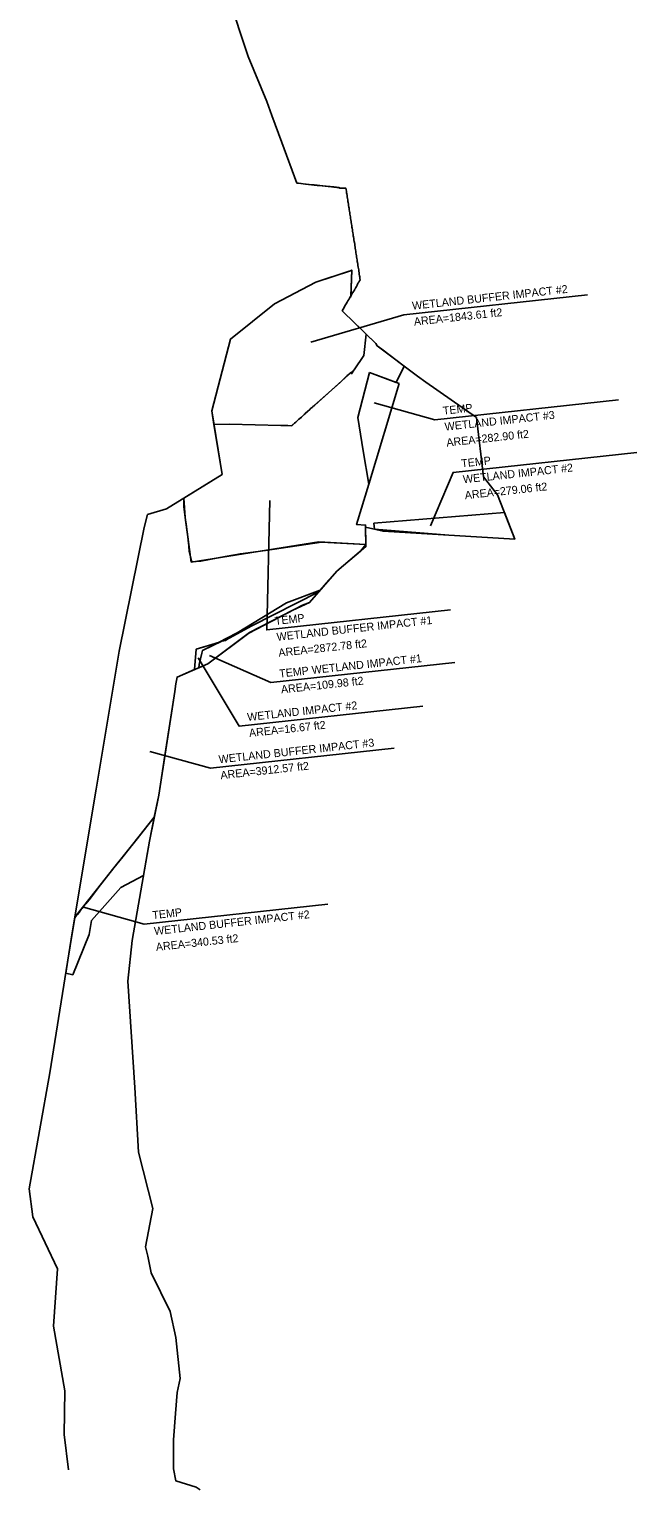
# Model space of a CAD drawing. Extents: x 1509173 to 1510536, y 401169 to 402191.
# Drawn here: x 1509752 to 1509965, y 401169 to 401680 of the extents above; entities that cross this region are included whole.
import ezdxf

# ---------------------------------------------------------------- set-up
doc = ezdxf.new("R2010")
doc.units = 0
for name, color, linetype in [('Default', 7, 'Continuous'), ('EWB_P', 7, 'Continuous'), ('LAWE', 7, 'Continuous'), ('LAWE_P_T', 7, 'Continuous'), ('Level 11', 7, 'Continuous'), ('Level 12', 7, 'Continuous')]:
    doc.layers.add(name, color=color, linetype=linetype)

msp = doc.modelspace()

# ---------------------------------------------------------------- linework, layer by layer
at = {"layer": 'Default'}
for p, q in [((1509864.2, 401595.49), (1509852.48, 401591.74)), ((1509864.65, 401595.7), (1509864.2, 401595.49)), ((1509865.1, 401595.9), (1509864.65, 401595.7)), ((1509864.8, 401586.93), (1509865.1, 401595.9)), ((1509852.48, 401591.74), (1509838.04, 401584.11)), ((1509838.04, 401584.11), (1509822.65, 401571.75)), ((1509862.07, 401582.21), (1509862.42, 401582.85)), ((1509862.42, 401582.85), (1509862.6, 401583.15)), ((1509862.6, 401583.15), (1509862.92, 401583.73)), ((1509862.92, 401583.73), (1509863.15, 401584.11)), ((1509863.72, 401585.12), (1509864.04, 401585.65)), ((1509864.04, 401585.65), (1509864.3, 401586.1)), ((1509864.3, 401586.1), (1509864.62, 401586.63)), ((1509864.62, 401586.63), (1509864.8, 401586.93)), ((1509861.77, 401581.65), (1509861.92, 401581.93)), ((1509866.19, 401577.38), (1509861.77, 401581.65)), ((1509861.92, 401581.93), (1509861.99, 401582.05)), ((1509861.99, 401582.05), (1509862.07, 401582.21)), ((1509867.89, 401575.71), (1509866.19, 401577.38)), ((1509870.13, 401573.51), (1509867.89, 401575.71)), ((1509870.13, 401573.51), (1509869.28, 401565.98)), ((1509869.28, 401565.98), (1509870.13, 401573.51)), ((1509873.47, 401570.24), (1509870.13, 401573.51)), ((1509822.65, 401571.75), (1509816.13, 401546.69)), ((1509883.44, 401562.33), (1509875.57, 401568.19)), ((1509869.28, 401565.98), (1509865.93, 401561.06)), ((1509865.93, 401561.06), (1509869.28, 401565.98)), ((1509880.68, 401556.6), (1509883.44, 401562.33)), ((1509862.26, 401557.72), (1509861.01, 401556.63)), ((1509863.51, 401558.99), (1509862.26, 401557.72)), ((1509863.9, 401559.21), (1509863.51, 401558.99)), ((1509864.39, 401559.68), (1509863.9, 401559.21)), ((1509864.6, 401559.92), (1509864.39, 401559.68)), ((1509864.84, 401560.02), (1509864.6, 401559.92)), ((1509864.96, 401560.21), (1509864.84, 401560.02)), ((1509865.07, 401559.75), (1509864.95, 401559.57)), ((1509865.34, 401560.58), (1509864.96, 401560.21)), ((1509865.19, 401559.94), (1509865.07, 401559.75)), ((1509865.31, 401560.13), (1509865.19, 401559.94)), ((1509865.47, 401560.71), (1509865.31, 401560.13)), ((1509865.43, 401560.31), (1509865.31, 401560.13)), ((1509865.31, 401560.13), (1509865.43, 401560.31)), ((1509865.56, 401560.5), (1509865.43, 401560.31)), ((1509865.68, 401560.68), (1509865.56, 401560.5)), ((1509865.81, 401560.87), (1509865.68, 401560.68)), ((1509865.93, 401561.06), (1509865.81, 401560.87)), ((1509865.81, 401560.87), (1509865.93, 401561.06)), ((1509867.19, 401544.37), (1509871.27, 401560.06)), ((1509871.27, 401560.06), (1509880.68, 401556.6)), ((1509855.56, 401551.74), (1509858.16, 401554.05)), ((1509849.59, 401546.38), (1509850.38, 401547.12)), ((1509851.03, 401547.73), (1509849.72, 401546.51)), ((1509850.38, 401547.12), (1509850.83, 401547.55)), ((1509850.83, 401547.55), (1509851.03, 401547.73)), ((1509851.03, 401547.73), (1509851.22, 401547.83)), ((1509851.22, 401547.83), (1509851.53, 401548.07)), ((1509851.53, 401548.07), (1509851.62, 401548.29)), ((1509851.62, 401548.29), (1509851.93, 401548.46)), ((1509851.93, 401548.46), (1509853.46, 401549.87)), ((1509853.46, 401549.87), (1509855.56, 401551.74)), ((1509816.13, 401546.69), (1509816.91, 401541.94)), ((1509816.91, 401541.94), (1509822.28, 401541.96)), ((1509822.28, 401541.96), (1509831.28, 401541.76)), ((1509844.18, 401541.47), (1509844.58, 401541.89)), ((1509844.58, 401541.89), (1509844.52, 401541.83)), ((1509844.58, 401541.89), (1509844.93, 401542.18)), ((1509844.91, 401542.18), (1509844.79, 401542.08)), ((1509845.11, 401542.33), (1509844.91, 401542.18)), ((1509844.93, 401542.18), (1509845.24, 401542.46)), ((1509845.38, 401542.58), (1509845.11, 401542.33)), ((1509845.24, 401542.46), (1509845.52, 401542.69)), ((1509845.52, 401542.69), (1509845.38, 401542.58)), ((1509846.08, 401543.23), (1509845.52, 401542.69)), ((1509845.52, 401542.69), (1509846.08, 401543.23)), ((1509846.64, 401543.78), (1509846.08, 401543.23)), ((1509846.08, 401543.23), (1509846.29, 401543.45)), ((1509846.29, 401543.45), (1509846.64, 401543.78)), ((1509847.36, 401544.36), (1509846.64, 401543.78)), ((1509846.64, 401543.78), (1509846.8, 401543.88)), ((1509846.64, 401543.78), (1509846.64, 401543.78)), ((1509846.8, 401543.88), (1509847, 401544.07)), ((1509846.8, 401543.88), (1509846.8, 401543.88)), ((1509846.8, 401543.88), (1509846.8, 401543.88)), ((1509847, 401544.07), (1509847.21, 401544.25)), ((1509847.21, 401544.25), (1509847.47, 401544.48)), ((1509847.21, 401544.25), (1509847.21, 401544.25)), ((1509847.21, 401544.25), (1509847.21, 401544.25)), ((1509847.21, 401544.25), (1509847.21, 401544.25)), ((1509847.21, 401544.25), (1509847.21, 401544.25)), ((1509848.79, 401545.7), (1509847.36, 401544.36)), ((1509847.47, 401544.48), (1509847.87, 401544.82)), ((1509847.87, 401544.82), (1509848.25, 401545.14)), ((1509848.25, 401545.14), (1509848.49, 401545.4)), ((1509848.49, 401545.4), (1509848.65, 401545.54)), ((1509848.65, 401545.54), (1509848.79, 401545.7)), ((1509849.72, 401546.51), (1509848.79, 401545.7)), ((1509848.79, 401545.7), (1509849.14, 401545.97)), ((1509848.79, 401545.7), (1509848.79, 401545.7)), ((1509849.14, 401545.97), (1509849.59, 401546.38)), ((1509869.13, 401532.65), (1509867.19, 401544.37)), ((1509831.28, 401541.76), (1509840.28, 401541.56)), ((1509840.78, 401541.55), (1509840.28, 401541.56)), ((1509840.28, 401541.56), (1509840.78, 401541.55)), ((1509842.77, 401541.51), (1509840.78, 401541.55)), ((1509840.78, 401541.55), (1509842.77, 401541.51)), ((1509844.18, 401541.47), (1509842.77, 401541.51)), ((1509842.77, 401541.51), (1509844.18, 401541.47)), ((1509844.19, 401541.54), (1509844.18, 401541.47)), ((1509844.18, 401541.47), (1509844.18, 401541.47)), ((1509844.18, 401541.47), (1509844.18, 401541.47)), ((1509844.28, 401541.63), (1509844.19, 401541.54)), ((1509844.19, 401541.54), (1509844.19, 401541.54)), ((1509844.32, 401541.66), (1509844.28, 401541.63)), ((1509844.38, 401541.72), (1509844.32, 401541.66)), ((1509844.44, 401541.77), (1509844.38, 401541.72)), ((1509844.52, 401541.83), (1509844.44, 401541.77)), ((1509871.05, 401520.99), (1509869.13, 401532.65)), ((1509800.27, 401512.41), (1509793.6, 401510.39)), ((1509806.38, 401516.16), (1509800.27, 401512.41)), ((1509806.38, 401516.16), (1509806.38, 401513.07)), ((1509808.89, 401493.77), (1509807.16, 401507.06)), ((1509807.53, 401504.25), (1509807.75, 401502.54)), ((1509807.75, 401502.54), (1509808.03, 401500.41)), ((1509808.03, 401500.41), (1509808.16, 401499.4)), ((1509808.16, 401499.4), (1509808.16, 401499.4)), ((1509808.16, 401499.4), (1509808.17, 401497.48)), ((1509808.17, 401497.48), (1509808.17, 401497.48)), ((1509853.64, 401500.79), (1509808.89, 401493.77)), ((1509870.02, 401499.95), (1509853.64, 401500.79)), ((1509862.23, 401492.56), (1509868.18, 401497.61)), ((1509812.26, 401494.11), (1509820.83, 401495.71)), ((1509859.53, 401490.15), (1509862.23, 401492.56)), ((1509854.09, 401483.91), (1509857.11, 401487.37)), ((1509857.11, 401487.37), (1509859.53, 401490.15)), ((1509810.68, 401463.32), (1509818.5, 401465.63)), ((1509818.5, 401465.63), (1509825.05, 401468.95)), ((1509810.05, 401456.13), (1509810.68, 401463.32)), ((1509803.99, 401453.51), (1509810.05, 401456.13)), ((1509803.17, 401448.44), (1509803.56, 401451.18)), ((1509803.56, 401451.18), (1509803.99, 401453.51)), ((1509799.71, 401426.05), (1509803.17, 401448.44)), ((1509797.57, 401412.24), (1509799.71, 401426.05)), ((1509796.8, 401408.39), (1509797.57, 401412.24)), ((1509785.01, 401390.63), (1509796.03, 401404.55)), ((1509796.03, 401404.55), (1509790.01, 401396.94)), ((1509794.34, 401396.07), (1509796.03, 401404.55)), ((1509796.03, 401404.55), (1509796.8, 401408.39)), ((1509790.01, 401396.94), (1509781.92, 401386.73)), ((1509793.65, 401392.16), (1509794.34, 401396.07)), ((1509781.92, 401386.73), (1509785.01, 401390.63)), ((1509775.84, 401379.03), (1509781.92, 401386.73)), ((1509781.92, 401386.73), (1509776.43, 401379.81)), ((1509776.43, 401379.81), (1509773.69, 401376.19)), ((1509771.76, 401373.87), (1509771.17, 401373.11)), ((1509772.04, 401374.22), (1509771.76, 401373.87)), ((1509773.69, 401376.19), (1509772.04, 401374.22)), ((1509768.18, 401369.34), (1509767.36, 401364.41)), ((1509768.66, 401369.95), (1509768.18, 401369.34)), ((1509768.18, 401369.34), (1509768.18, 401369.34)), ((1509768.18, 401369.34), (1509768.18, 401369.34)), ((1509769, 401370.29), (1509768.66, 401369.95)), ((1509769.7, 401371.18), (1509769, 401370.29)), ((1509770.08, 401371.75), (1509769.7, 401371.18)), ((1509770.6, 401372.4), (1509770.08, 401371.75)), ((1509770.82, 401372.68), (1509770.6, 401372.4)), ((1509771.17, 401373.11), (1509770.74, 401372.58)), ((1509770.74, 401372.58), (1509771.03, 401372.94)), ((1509771.07, 401372.99), (1509770.82, 401372.68)), ((1509771.03, 401372.94), (1509771.21, 401373.18)), ((1509771.21, 401373.18), (1509771.07, 401372.99)), ((1509765.06, 401349.9), (1509767.58, 401349.35))]:
    msp.add_line(p, q, dxfattribs=at)
for points in [[(1509863.15, 401584.11), (1509863.47, 401584.68), (1509863.72, 401585.12)], [(1509875.57, 401568.19), (1509873.96, 401569.39), (1509873.47, 401570.24)], [(1509858.16, 401554.05), (1509865.16, 401560.26), (1509865.47, 401560.71)], [(1509864.95, 401559.57), (1509865.68, 401560.68), (1509865.56, 401560.5), (1509865.34, 401560.58)], [(1509865.43, 401560.31), (1509865.56, 401560.5), (1509865.68, 401560.68), (1509865.81, 401560.87)], [(1509861.01, 401556.63), (1509851.03, 401547.73)], [(1509816.91, 401541.94), (1509819.81, 401524.41), (1509806.38, 401516.16)], [(1509840.28, 401541.56), (1509831.28, 401541.76), (1509822.28, 401541.96), (1509816.91, 401541.94)], [(1509844.79, 401542.08), (1509844.71, 401542.01), (1509844.58, 401541.89)], [(1509820.83, 401495.71), (1509826.14, 401496.68), (1509834.96, 401497.8), (1509854.5, 401500.75), (1509870.02, 401499.95), (1509869.95, 401506.67), (1509866.77, 401506.88), (1509871.05, 401520.99)], [(1509807.16, 401507.06), (1509806.87, 401509.32), (1509806.38, 401516.16)], [(1509806.38, 401513.07), (1509806.99, 401508.42), (1509807.53, 401504.25)], [(1509793.6, 401510.39), (1509792.46, 401505.8), (1509783.79, 401462.54), (1509768.2, 401369.5), (1509775.84, 401379.03)], [(1509808.17, 401497.48), (1509809.13, 401493.81), (1509812.26, 401494.11)], [(1509868.18, 401497.61), (1509870.02, 401499.95)], [(1509825.05, 401468.95), (1509842.22, 401479.49), (1509854.09, 401483.91)], [(1509767.58, 401349.35), (1509773.28, 401363.45), (1509774.1, 401368.36), (1509784.28, 401379.94), (1509792.24, 401384.13), (1509793.65, 401392.16)], [(1509767.36, 401364.41), (1509766.58, 401359.47), (1509765.8, 401354.53), (1509765.06, 401349.9)]]:
    msp.add_lwpolyline(points, dxfattribs=at)
at = {"layer": 'EWB_P'}
for points in [[(1509793.6, 401510.39), (1509800.27, 401512.41), (1509819.81, 401524.41), (1509816.13, 401546.69), (1509822.65, 401571.75), (1509838.04, 401584.11), (1509852.48, 401591.74), (1509864.65, 401595.7), (1509865.1, 401595.9), (1509864.78, 401586.49)], [(1509793.6, 401510.39), (1509792.46, 401505.8), (1509783.79, 401462.54), (1509775.66, 401414.3), (1509767.41, 401364.72), (1509759.54, 401315.03), (1509752.27, 401274.51)], [(1509765.96, 401176.14), (1509764.55, 401188.49), (1509764.79, 401203.85), (1509760.76, 401226.38), (1509762.22, 401246.45), (1509753.5, 401264.74), (1509752.27, 401274.51)]]:
    msp.add_lwpolyline(points, dxfattribs=at)
at = {"layer": 'LAWE'}
msp.add_lwpolyline([(1509812.05, 401169.19), (1509810.71, 401170.16), (1509803.59, 401172.29), (1509802.78, 401176.52), (1509802.79, 401186.66), (1509803.48, 401195.88), (1509804.04, 401203.26), (1509805.07, 401208.1), (1509803.51, 401222.5), (1509801.55, 401231.55), (1509794.98, 401245.1), (1509793.76, 401250.98), (1509793, 401254.21), (1509795.55, 401267.57), (1509790.47, 401287.33), (1509789.26, 401309.93), (1509786.81, 401347.16), (1509788.24, 401361.35), (1509794.34, 401396.07), (1509797.57, 401412.24), (1509803.17, 401448.44), (1509803.56, 401451.18), (1509803.99, 401453.51), (1509814.78, 401458.16), (1509829.08, 401468.94), (1509847.87, 401478.69), (1509850.37, 401479.63), (1509859.92, 401490.6), (1509870.03, 401499.17), (1509869.96, 401505.96), (1509876.07, 401504.54), (1509922.14, 401501.76), (1509916.13, 401517.28), (1509911.17, 401523.54), (1509908.75, 401544.3), (1509891.05, 401556.7), (1509888.15, 401558.82), (1509873.96, 401569.39), (1509873.47, 401570.24), (1509866.19, 401577.38), (1509861.77, 401581.65), (1509862.07, 401582.21), (1509862.42, 401582.85), (1509862.6, 401583.15), (1509862.92, 401583.73), (1509863.15, 401584.11), (1509863.47, 401584.68), (1509863.72, 401585.12), (1509864.04, 401585.65), (1509864.3, 401586.1), (1509864.62, 401586.63), (1509864.88, 401587.07), (1509865.17, 401587.55), (1509865.45, 401588.01), (1509865.73, 401588.46), (1509866.01, 401588.93), (1509866.07, 401589.06), (1509866.27, 401589.39), (1509866.51, 401589.84), (1509866.72, 401590.17), (1509866.96, 401590.62), (1509867.16, 401590.95), (1509867.4, 401591.4), (1509867.6, 401591.73), (1509867.85, 401592.18), (1509868.05, 401592.51), (1509867.98, 401592.94), (1509867.89, 401593.51), (1509867.83, 401593.94), (1509867.74, 401594.51), (1509867.67, 401594.94), (1509867.58, 401595.51), (1509867.52, 401595.94), (1509867.42, 401596.52), (1509867.36, 401596.94), (1509867.27, 401597.52), (1509867.21, 401597.94), (1509867.11, 401598.52), (1509867.05, 401598.94), (1509866.96, 401599.52), (1509866.89, 401599.95), (1509866.8, 401600.52), (1509866.74, 401600.95), (1509866.65, 401601.52), (1509866.58, 401601.95), (1509866.49, 401602.52), (1509866.43, 401602.95), (1509866.33, 401603.52), (1509866.27, 401603.95), (1509866.18, 401604.52), (1509866.12, 401604.95), (1509866.02, 401605.52), (1509865.96, 401605.95), (1509865.87, 401606.53), (1509865.8, 401606.95), (1509865.71, 401607.53), (1509865.65, 401607.95), (1509865.56, 401608.53), (1509865.49, 401608.95), (1509865.4, 401609.53), (1509865.34, 401609.95), (1509865.24, 401610.53), (1509865.18, 401610.95), (1509865.09, 401611.53), (1509865.03, 401611.95), (1509864.93, 401612.53), (1509864.87, 401612.95), (1509864.78, 401613.53), (1509864.71, 401613.96), (1509864.62, 401614.53), (1509864.56, 401614.96), (1509864.46, 401615.53), (1509864.4, 401615.96), (1509864.31, 401616.53), (1509864.25, 401616.96), (1509864.15, 401617.54), (1509864.09, 401617.96), (1509864, 401618.54), (1509863.94, 401618.96), (1509863.84, 401619.54), (1509863.78, 401619.96), (1509863.69, 401620.54), (1509863.62, 401620.96), (1509863.53, 401621.54), (1509863.47, 401621.96), (1509863.37, 401622.54), (1509863.31, 401622.96), (1509863.22, 401623.54), (1509863.16, 401623.96), (1509863.06, 401624.54), (1509862.66, 401624.58), (1509862.15, 401624.56), (1509861.73, 401624.6), (1509861.24, 401624.58), (1509860.8, 401624.62), (1509860.7, 401624.78), (1509860, 401624.86), (1509859.7, 401624.89), (1509858.98, 401624.96), (1509858.7, 401625), (1509857.97, 401625.07), (1509857.6, 401625.11), (1509856.87, 401625.18), (1509856.13, 401625.26), (1509855.78, 401625.3), (1509855.03, 401625.37), (1509854.7, 401625.41), (1509853.95, 401625.48), (1509853.17, 401625.56), (1509852.88, 401625.6), (1509852.09, 401625.67), (1509851.81, 401625.7), (1509851.03, 401625.78), (1509850.21, 401625.86), (1509849.97, 401625.89), (1509849.15, 401625.97), (1509848.93, 401626), (1509848.11, 401626.08), (1509847.37, 401626.17), (1509847.24, 401626.19), (1509846.49, 401626.29), (1509845.93, 401626.36), (1509840.68, 401640.55), (1509837.17, 401650.02), (1509835.36, 401654.93), (1509828.91, 401670.68), (1509826.52, 401677.61), (1509814.57, 401714.41)], dxfattribs=at)
at = {"layer": 'LAWE_P_T'}
for points in [[(1509850.8, 401570.65), (1509883.34, 401580.3), (1509947.61, 401587.3)], [(1509872.95, 401549.44), (1509894.12, 401543.55), (1509958.39, 401550.56)], [(1509892.66, 401506.39), (1509900.53, 401525.13), (1509964.8, 401532.13)], [(1509836.39, 401515.26), (1509835.35, 401470.02), (1509899.63, 401477.03)], [(1509811.33, 401460.27), (1509825.68, 401436.38), (1509889.96, 401443.39)], [(1509815.34, 401461.07), (1509836.85, 401451.6), (1509901.12, 401458.61)], [(1509794.51, 401427.49), (1509815.68, 401421.61), (1509879.96, 401428.61)], [(1509771.31, 401372.97), (1509792.48, 401367.08), (1509856.75, 401374.09)]]:
    msp.add_lwpolyline(points, dxfattribs=at)
at = {"layer": 'Level 11'}
for p, q in [((1509810.68, 401463.32), (1509810.05, 401456.13)), ((1509812.26, 401463.79), (1509810.68, 401463.32)), ((1509811.71, 401457.95), (1509812.64, 401461.85)), ((1509810.05, 401456.13), (1509811.59, 401456.79)), ((1509811.59, 401456.79), (1509811.71, 401457.95))]:
    msp.add_line(p, q, dxfattribs=at)
msp.add_lwpolyline([(1509812.64, 401461.85), (1509812.91, 401462.82), (1509818.78, 401465.77), (1509812.26, 401463.79)], dxfattribs=at)
at = {"layer": 'Level 12'}
for p, q in [((1509871.27, 401560.06), (1509867.19, 401544.37)), ((1509881.74, 401556.22), (1509871.27, 401560.06)), ((1509867.19, 401544.37), (1509869.13, 401532.65)), ((1509918.51, 401511.14), (1509872.77, 401507.37)), ((1509872.77, 401507.37), (1509873.02, 401505.25)), ((1509873.02, 401505.25), (1509899.11, 401503.15)), ((1509819.68, 401466.05), (1509812.91, 401462.82)), ((1509812.91, 401462.82), (1509812.91, 401462.82))]:
    msp.add_line(p, q, dxfattribs=at)
for points in [[(1509869.13, 401532.65), (1509871.05, 401520.99), (1509881.74, 401556.22)], [(1509899.11, 401503.15), (1509922.14, 401501.76), (1509918.51, 401511.14)], [(1509818.66, 401461.09), (1509829.37, 401469.09), (1509844.5, 401476.94), (1509850.33, 401479.62), (1509853.59, 401483.3), (1509829.93, 401471.39), (1509821.18, 401466.57), (1509821.09, 401466.32), (1509819.68, 401466.05)], [(1509812.91, 401462.82), (1509812.64, 401461.85), (1509811.71, 401457.95), (1509811.59, 401456.79)], [(1509811.59, 401456.79), (1509814.78, 401458.16), (1509818.66, 401461.09)]]:
    msp.add_lwpolyline(points, dxfattribs=at)

# ---------------------------------------------------------------- texts
at = {"layer": 'LAWE_P_T'}
for s, p in [('WETLAND BUFFER IMPACT #2', (1509886.36, 401582.03)), ('AREA=1843.61 ft2', (1509886.97, 401576.47)), ('TEMP', (1509897.14, 401545.29)), ('WETLAND IMPACT #3', (1509897.75, 401539.72)), ('AREA=282.90 ft2', (1509898.35, 401534.15)), ('TEMP', (1509903.55, 401526.86)), ('WETLAND IMPACT #2', (1509904.16, 401521.3)), ('AREA=279.06 ft2', (1509904.77, 401515.73)), ('TEMP', (1509838.37, 401471.76)), ('WETLAND BUFFER IMPACT #1', (1509838.98, 401466.19)), ('AREA=2872.78 ft2', (1509839.59, 401460.62)), ('TEMP WETLAND IMPACT #1', (1509839.87, 401453.34)), ('AREA=109.98 ft2', (1509840.48, 401447.78)), ('WETLAND IMPACT #2', (1509828.7, 401438.12)), ('AREA=16.67 ft2', (1509829.31, 401432.56)), ('WETLAND BUFFER IMPACT #3', (1509818.7, 401423.34)), ('AREA=3912.57 ft2', (1509819.31, 401417.78)), ('TEMP', (1509795.5, 401368.82)), ('WETLAND BUFFER IMPACT #2', (1509796.11, 401363.25)), ('AREA=340.53 ft2', (1509796.72, 401357.69))]:
    msp.add_text(s, height=2.8, rotation=6.2219, dxfattribs=at).set_placement(p)

doc.saveas('drawing.dxf')
